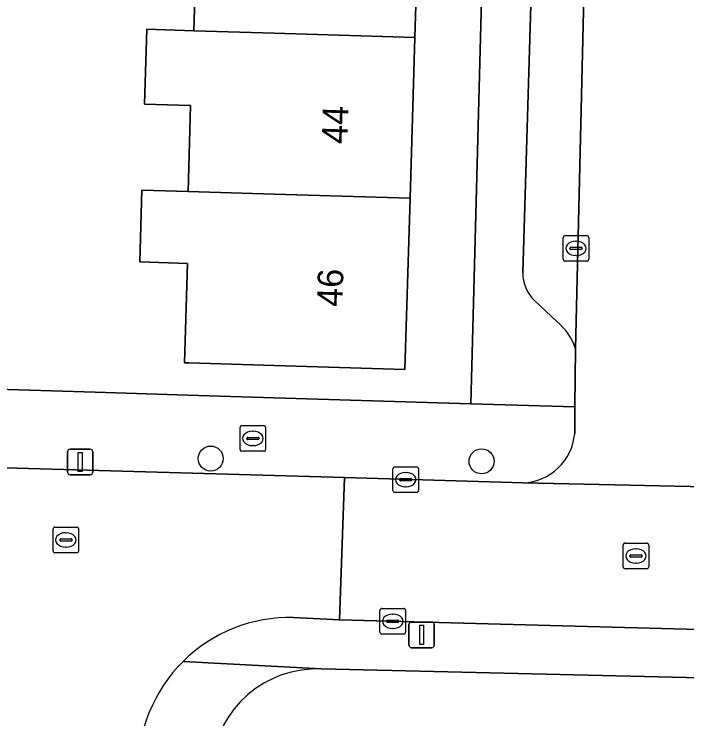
# Model space of a CAD drawing. Extents: x 162082 to 163401, y 388089 to 388636.
# Drawn here: x 162489.83 to 162516.16, y 388190.03 to 388217.6 of the extents above; entities that cross this region are included whole.
import ezdxf

# ---------------------------------------------------------------- set-up
doc = ezdxf.new("R2010")
doc.units = 0
for name, color, linetype in [('IMGEO_Boom', 7, 'Continuous'), ('IMGEO_Brandkraan', 7, 'Continuous'), ('IMGEO_Erf', 7, 'Continuous'), ('IMGEO_Groenvoorziening', 7, 'Continuous'), ('IMGEO_Kolk', 7, 'Continuous'), ('IMGEO_Lichtmast', 7, 'Continuous'), ('IMGEO_Pand', 7, 'Continuous'), ('IMGEO_Pand_nummerreeks', 7, 'Continuous'), ('IMGEO_Parkeervlak_open', 7, 'Continuous'), ('IMGEO_Rijbaan_lokaal_open', 7, 'Continuous'), ('IMGEO_Rioolput', 7, 'Continuous'), ('IMGEO_Voetpad_open', 7, 'Continuous')]:
    doc.layers.add(name, color=color, linetype=linetype)

msp = doc.modelspace()

# ---------------------------------------------------------------- linework, layer by layer
at = {"layer": 'IMGEO_Boom'}
for centre in [(162497.524, 388200.209), (162508.119, 388200.102)]:
    msp.add_circle(centre, 0.489, dxfattribs=at)
at = {"layer": 'IMGEO_Brandkraan'}
for p, q in [((162498.746, 388201.496), (162499.598, 388201.496)), ((162498.671, 388200.57), (162498.671, 388201.422)), ((162499.159, 388201.276), (162499.184, 388201.276)), ((162499.672, 388201.422), (162499.672, 388200.57)), ((162498.93, 388200.99), (162498.93, 388201.002)), ((162499.368, 388200.953), (162498.97, 388200.953)), ((162498.973, 388201.039), (162499.371, 388201.039)), ((162499.414, 388201.002), (162499.414, 388200.99)), ((162499.182, 388200.716), (162499.157, 388200.716)), ((162499.598, 388200.496), (162498.746, 388200.496))]:
    msp.add_line(p, q, dxfattribs=at)
for points in [[(162498.746, 388201.496), (162499.598, 388201.496)], [(162498.671, 388200.57), (162498.671, 388201.422)], [(162499.672, 388201.422), (162499.672, 388200.57)], [(162499.598, 388200.496), (162498.746, 388200.496)]]:
    msp.add_lwpolyline(points, dxfattribs=at)
for centre, radius, start, end in [((162498.748, 388201.42), 0.0765, 91.552, 178.448), ((162498.748, 388201.42), 0.0765, 91.552, 178.448), ((162499.596, 388201.42), 0.0765, 1.552, 88.448), ((162499.596, 388201.42), 0.0765, 1.552, 88.448), ((162498.97, 388200.999), 0.0403, 85.8775, 175.7526), ((162498.967, 388200.989), 0.0366, 178.938, 274.7102), ((162499.371, 388200.996), 0.043, 264.8664, 352.4533), ((162499.375, 388201.001), 0.0386, 1.7309, 96.639), ((162498.748, 388200.572), 0.0765, 181.552, 268.448), ((162498.748, 388200.572), 0.0765, 181.552, 268.448), ((162499.596, 388200.572), 0.0765, 271.552, 358.448), ((162499.596, 388200.572), 0.0765, 271.552, 358.448)]:
    msp.add_arc(centre, radius, start, end, dxfattribs=at)
for centre, major_axis, ratio, start_param, end_param in [((162499.158, 388200.996), (-0.387, 0.002), 0.722429, 4.712389, 7.853982), ((162499.183, 388200.996), (-0.39, 0.002), 0.717154, 1.570796, 4.712389)]:
    msp.add_ellipse(centre, major_axis=major_axis, ratio=ratio, start_param=start_param, end_param=end_param, dxfattribs=at)
at = {"layer": 'IMGEO_Erf'}
for points in [[(162488.717, 388202.931), (162492.996, 388202.801), (162496.624, 388202.69), (162500, 388202.587), (162507.697, 388202.352), (162508.569, 388235.464)], [(162505.708, 388223.014), (162505.515, 388216.682), (162505.324, 388210.391), (162505.121, 388203.697), (162500, 388203.853), (162496.665, 388203.954), (162496.498, 388203.959), (162496.616, 388207.844), (162494.747, 388207.901), (162494.832, 388210.71), (162496.635, 388210.655), (162496.737, 388214.022), (162494.928, 388214.077), (162495.017, 388217.001), (162496.862, 388216.945), (162496.967, 388220.408)]]:
    msp.add_lwpolyline(points, dxfattribs=at)
at = {"layer": 'IMGEO_Groenvoorziening'}
msp.add_lwpolyline([(162546.46, 388190.85), (162524.934, 388191.433), (162501.862, 388191.979)], dxfattribs=at)
msp.add_arc((162501.682, 388187.838), 4.145, 87.5092, 174.1806, dxfattribs=at)
at = {"layer": 'IMGEO_Kolk'}
for p, q in [((162511.39, 388208.929), (162512.242, 388208.929)), ((162511.315, 388208.003), (162511.315, 388208.855)), ((162511.803, 388208.709), (162511.828, 388208.709)), ((162512.316, 388208.855), (162512.316, 388208.003)), ((162511.574, 388208.423), (162511.574, 388208.435)), ((162512.012, 388208.386), (162511.614, 388208.386)), ((162511.617, 388208.472), (162512.015, 388208.472)), ((162512.058, 388208.435), (162512.058, 388208.423)), ((162511.826, 388208.149), (162511.801, 388208.149)), ((162512.242, 388207.929), (162511.39, 388207.929)), ((162504.653, 388198.958), (162504.653, 388199.81)), ((162504.728, 388199.884), (162505.58, 388199.884)), ((162505.654, 388199.81), (162505.654, 388198.958)), ((162505.141, 388199.664), (162505.166, 388199.664)), ((162504.912, 388199.378), (162504.912, 388199.39)), ((162505.35, 388199.341), (162504.952, 388199.341)), ((162504.955, 388199.427), (162505.353, 388199.427)), ((162505.396, 388199.39), (162505.396, 388199.378)), ((162505.164, 388199.104), (162505.139, 388199.104)), ((162505.58, 388198.884), (162504.728, 388198.884)), ((162504.221, 388194.345), (162505.073, 388194.345)), ((162504.146, 388193.419), (162504.146, 388194.271)), ((162504.634, 388194.125), (162504.659, 388194.125)), ((162505.147, 388194.271), (162505.147, 388193.419)), ((162504.405, 388193.839), (162504.405, 388193.851)), ((162504.843, 388193.802), (162504.445, 388193.802)), ((162504.448, 388193.888), (162504.846, 388193.888)), ((162504.889, 388193.851), (162504.889, 388193.839)), ((162504.657, 388193.565), (162504.632, 388193.565)), ((162505.073, 388193.345), (162504.221, 388193.345))]:
    msp.add_line(p, q, dxfattribs=at)
for points in [[(162511.39, 388208.929), (162512.242, 388208.929)], [(162511.315, 388208.003), (162511.315, 388208.855)], [(162512.316, 388208.855), (162512.316, 388208.003)], [(162512.242, 388207.929), (162511.39, 388207.929)], [(162504.653, 388198.958), (162504.653, 388199.81)], [(162504.728, 388199.884), (162505.58, 388199.884)], [(162505.654, 388199.81), (162505.654, 388198.958)], [(162505.58, 388198.884), (162504.728, 388198.884)], [(162504.221, 388194.345), (162505.073, 388194.345)], [(162504.146, 388193.419), (162504.146, 388194.271)], [(162505.147, 388194.271), (162505.147, 388193.419)], [(162505.073, 388193.345), (162504.221, 388193.345)]]:
    msp.add_lwpolyline(points, dxfattribs=at)
for centre, radius, start, end in [((162511.392, 388208.853), 0.0765, 91.552, 178.448), ((162511.392, 388208.853), 0.0765, 91.552, 178.448), ((162512.24, 388208.853), 0.0765, 1.552, 88.448), ((162512.24, 388208.853), 0.0765, 1.552, 88.448), ((162511.614, 388208.432), 0.0403, 85.8775, 175.7526), ((162511.611, 388208.422), 0.0366, 178.938, 274.7102), ((162512.015, 388208.429), 0.043, 264.8664, 352.4533), ((162512.019, 388208.434), 0.0386, 1.7309, 96.639), ((162511.392, 388208.005), 0.0765, 181.552, 268.448), ((162511.392, 388208.005), 0.0765, 181.552, 268.448), ((162512.24, 388208.005), 0.0765, 271.552, 358.448), ((162512.24, 388208.005), 0.0765, 271.552, 358.448), ((162504.73, 388199.808), 0.0765, 91.552, 178.448), ((162504.73, 388199.808), 0.0765, 91.552, 178.448), ((162505.578, 388199.808), 0.0765, 1.552, 88.448), ((162505.578, 388199.808), 0.0765, 1.552, 88.448), ((162504.952, 388199.387), 0.0403, 85.8775, 175.7526), ((162504.949, 388199.377), 0.0366, 178.938, 274.7102), ((162505.353, 388199.384), 0.043, 264.8664, 352.4533), ((162505.357, 388199.389), 0.0386, 1.7309, 96.639), ((162504.73, 388198.96), 0.0765, 181.552, 268.448), ((162504.73, 388198.96), 0.0765, 181.552, 268.448), ((162505.578, 388198.96), 0.0765, 271.552, 358.448), ((162505.578, 388198.96), 0.0765, 271.552, 358.448), ((162504.223, 388194.269), 0.0765, 91.552, 178.448), ((162504.223, 388194.269), 0.0765, 91.552, 178.448), ((162505.071, 388194.269), 0.0765, 1.552, 88.448), ((162505.071, 388194.269), 0.0765, 1.552, 88.448), ((162504.445, 388193.848), 0.0403, 85.8775, 175.7526), ((162504.442, 388193.838), 0.0366, 178.938, 274.7102), ((162504.846, 388193.845), 0.043, 264.8664, 352.4533), ((162504.85, 388193.85), 0.0386, 1.7309, 96.639), ((162504.223, 388193.421), 0.0765, 181.552, 268.448), ((162504.223, 388193.421), 0.0765, 181.552, 268.448), ((162505.071, 388193.421), 0.0765, 271.552, 358.448), ((162505.071, 388193.421), 0.0765, 271.552, 358.448)]:
    msp.add_arc(centre, radius, start, end, dxfattribs=at)
for centre, major_axis, ratio, start_param, end_param in [((162511.802, 388208.429), (-0.387, 0.002), 0.722429, 4.712389, 7.853982), ((162511.827, 388208.429), (-0.39, 0.002), 0.717154, 1.570796, 4.712389), ((162505.14, 388199.384), (-0.387, 0.002), 0.722429, 4.712389, 7.853982), ((162505.165, 388199.384), (-0.39, 0.002), 0.717154, 1.570796, 4.712389), ((162504.633, 388193.845), (-0.387, 0.002), 0.722429, 4.712389, 7.853982), ((162504.658, 388193.845), (-0.39, 0.002), 0.717154, 1.570796, 4.712389)]:
    msp.add_ellipse(centre, major_axis=major_axis, ratio=ratio, start_param=start_param, end_param=end_param, dxfattribs=at)
at = {"layer": 'IMGEO_Lichtmast'}
for p, q in [((162491.92, 388199.677), (162491.92, 388200.477)), ((162491.92, 388200.477), (162491.92, 388199.677)), ((162492.02, 388200.577), (162492.81, 388200.577)), ((162492.81, 388200.577), (162492.02, 388200.577)), ((162492.91, 388200.477), (162492.91, 388199.677)), ((162492.91, 388199.677), (162492.91, 388200.477)), ((162492.81, 388199.577), (162492.02, 388199.577)), ((162492.02, 388199.577), (162492.81, 388199.577)), ((162505.38, 388193.812), (162506.17, 388193.812)), ((162506.17, 388193.812), (162505.38, 388193.812)), ((162505.28, 388192.912), (162505.28, 388193.712)), ((162505.28, 388193.712), (162505.28, 388192.912)), ((162506.27, 388193.712), (162506.27, 388192.912)), ((162506.27, 388192.912), (162506.27, 388193.712)), ((162506.17, 388192.812), (162505.38, 388192.812)), ((162505.38, 388192.812), (162506.17, 388192.812))]:
    msp.add_line(p, q, dxfattribs=at)
for points in [[(162492.34, 388200.452), (162492.49, 388200.452), (162492.49, 388199.702), (162492.34, 388199.702), (162492.34, 388200.452)], [(162505.7, 388193.687), (162505.85, 388193.687), (162505.85, 388192.937), (162505.7, 388192.937), (162505.7, 388193.687)]]:
    msp.add_lwpolyline(points, dxfattribs=at)
for centre, start, end in [((162492.02, 388200.477), 90, 180), ((162492.02, 388200.477), 90, 180), ((162492.81, 388200.477), 0, 90), ((162492.81, 388200.477), 360, 90), ((162492.02, 388199.677), 180, 270), ((162492.02, 388199.677), 180, 270), ((162492.81, 388199.677), 270, 0), ((162492.81, 388199.677), 270, 0), ((162505.38, 388193.712), 90, 180), ((162505.38, 388193.712), 90, 180), ((162506.17, 388193.712), 0, 90), ((162506.17, 388193.712), 360, 90), ((162505.38, 388192.912), 180, 270), ((162505.38, 388192.912), 180, 270), ((162506.17, 388192.912), 270, 0), ((162506.17, 388192.912), 270, 0)]:
    msp.add_arc(centre, 0.1, start, end, dxfattribs=at)
at = {"layer": 'IMGEO_Pand'}
for points in [[(162496.862, 388216.945), (162500, 388216.85), (162505.515, 388216.682), (162505.708, 388223.014), (162500, 388223.188), (162497.078, 388223.277), (162495.183, 388223.334), (162495.096, 388220.465), (162496.967, 388220.408)], [(162505.324, 388210.391), (162505.515, 388216.682), (162500, 388216.85), (162496.862, 388216.945), (162495.017, 388217.001), (162494.928, 388214.077), (162496.737, 388214.022), (162496.635, 388210.655), (162500, 388210.553)], [(162494.747, 388207.901), (162496.616, 388207.844), (162496.498, 388203.959), (162496.665, 388203.954), (162500, 388203.853), (162505.121, 388203.697), (162505.324, 388210.391), (162500, 388210.553), (162496.635, 388210.655), (162494.832, 388210.71)]]:
    msp.add_lwpolyline(points, close=True, dxfattribs=at)
at = {"layer": 'IMGEO_Parkeervlak_open'}
for points in [[(162511.796, 388204.501), (162512.513, 388234.788)], [(162510.468, 388231.904), (162509.733, 388207.472)], [(162510.191, 388206.392), (162511.067, 388205.566)]]:
    msp.add_lwpolyline(points, dxfattribs=at)
for centre, radius, start, end in [((162511.195, 388207.455), 1.463, 179.3365, 226.6246), ((162509.635, 388203.804), 2.271, 17.8845, 50.8993)]:
    msp.add_arc(centre, radius, start, end, dxfattribs=at)
at = {"layer": 'IMGEO_Rijbaan_lokaal_open'}
for points in [[(162520.97, 388251.082), (162523.708, 388250.998), (162523.949, 388263.251), (162523.951, 388263.357), (162520.756, 388263.421), (162517.642, 388263.483), (162517.379, 388256.082), (162515.88, 388256.099), (162515.857, 388256.099), (162515.778, 388251.974), (162513.143, 388251.993), (162513.096, 388250), (162513.064, 388248.609), (162512.682, 388241.193), (162512.513, 388234.788), (162511.796, 388204.501), (162511.775, 388202.228), (162511.765, 388201.183)], [(162500.767, 388193.994), (162502.568, 388193.897), (162502.759, 388199.464), (162488.548, 388199.879), (162473.935, 388200.262), (162473.05, 388200.285), (162472.938, 388194.261), (162482.226, 388193.997), (162482.636, 388194.002)], [(162509.749, 388199.255), (162518.668, 388199.069)]]:
    msp.add_lwpolyline(points, dxfattribs=at)
msp.add_lwpolyline([(162583.027, 388197.416), (162571.264, 388197.644), (162571.167, 388197.718), (162554.857, 388198.059), (162553.864, 388198.076), (162538.01, 388198.533), (162519.576, 388198.987), (162518.668, 388199.069), (162509.749, 388199.255), (162502.759, 388199.464), (162502.568, 388193.897), (162582.601, 388191.752), (162582.769, 388195.348), (162582.974, 388195.545)], close=True, dxfattribs=at)
for centre, radius, start, end in [((162509.653, 388201.373), 2.12, 272.5848, 354.8588), ((162500.627, 388188.053), 5.942, 88.65, 134.825), ((162500.626, 388188.052), 5.943, 134.8061, 180.9792)]:
    msp.add_arc(centre, radius, start, end, dxfattribs=at)
at = {"layer": 'IMGEO_Rioolput'}
for p, q in [((162491.354, 388196.601), (162491.354, 388197.453)), ((162491.429, 388197.527), (162492.281, 388197.527)), ((162491.842, 388197.307), (162491.867, 388197.307)), ((162492.355, 388197.453), (162492.355, 388196.601)), ((162491.613, 388197.021), (162491.613, 388197.033)), ((162491.656, 388197.07), (162492.054, 388197.07)), ((162492.097, 388197.033), (162492.097, 388197.021)), ((162492.051, 388196.984), (162491.653, 388196.984)), ((162513.661, 388195.974), (162513.661, 388196.826)), ((162513.736, 388196.9), (162514.588, 388196.9)), ((162514.662, 388196.826), (162514.662, 388195.974)), ((162492.281, 388196.527), (162491.429, 388196.527)), ((162491.865, 388196.747), (162491.84, 388196.747)), ((162514.149, 388196.68), (162514.174, 388196.68)), ((162513.92, 388196.394), (162513.92, 388196.406)), ((162514.358, 388196.357), (162513.96, 388196.357)), ((162513.963, 388196.443), (162514.361, 388196.443)), ((162514.404, 388196.406), (162514.404, 388196.394)), ((162514.172, 388196.12), (162514.147, 388196.12)), ((162514.588, 388195.9), (162513.736, 388195.9))]:
    msp.add_line(p, q, dxfattribs=at)
for points in [[(162491.354, 388196.601), (162491.354, 388197.453)], [(162491.429, 388197.527), (162492.281, 388197.527)], [(162492.355, 388197.453), (162492.355, 388196.601)], [(162513.661, 388195.974), (162513.661, 388196.826)], [(162513.736, 388196.9), (162514.588, 388196.9)], [(162514.662, 388196.826), (162514.662, 388195.974)], [(162492.281, 388196.527), (162491.429, 388196.527)], [(162514.588, 388195.9), (162513.736, 388195.9)]]:
    msp.add_lwpolyline(points, dxfattribs=at)
for centre, radius, start, end in [((162491.431, 388197.451), 0.0765, 91.552, 178.448), ((162491.431, 388197.451), 0.0765, 91.552, 178.448), ((162492.279, 388197.451), 0.0765, 1.552, 88.448), ((162492.279, 388197.451), 0.0765, 1.552, 88.448), ((162491.653, 388197.03), 0.0403, 85.8775, 175.7526), ((162492.058, 388197.032), 0.0386, 1.7309, 96.639), ((162491.65, 388197.02), 0.0366, 178.938, 274.7102), ((162492.054, 388197.027), 0.043, 264.8664, 352.4533), ((162513.738, 388196.824), 0.0765, 91.552, 178.448), ((162513.738, 388196.824), 0.0765, 91.552, 178.448), ((162514.586, 388196.824), 0.0765, 1.552, 88.448), ((162514.586, 388196.824), 0.0765, 1.552, 88.448), ((162491.431, 388196.603), 0.0765, 181.552, 268.448), ((162491.431, 388196.603), 0.0765, 181.552, 268.448), ((162492.279, 388196.603), 0.0765, 271.552, 358.448), ((162492.279, 388196.603), 0.0765, 271.552, 358.448), ((162513.96, 388196.403), 0.0403, 85.8775, 175.7526), ((162513.957, 388196.393), 0.0366, 178.938, 274.7102), ((162514.361, 388196.4), 0.043, 264.8664, 352.4533), ((162514.365, 388196.405), 0.0386, 1.7309, 96.639), ((162513.738, 388195.976), 0.0765, 181.552, 268.448), ((162513.738, 388195.976), 0.0765, 181.552, 268.448), ((162514.586, 388195.976), 0.0765, 271.552, 358.448), ((162514.586, 388195.976), 0.0765, 271.552, 358.448)]:
    msp.add_arc(centre, radius, start, end, dxfattribs=at)
for centre, major_axis, ratio, start_param, end_param in [((162491.841, 388197.027), (-0.387, 0.002), 0.722429, 4.712389, 7.853982), ((162491.866, 388197.027), (-0.39, 0.002), 0.717154, 1.570796, 4.712389), ((162514.148, 388196.4), (-0.387, 0.002), 0.722429, 4.712389, 7.853982), ((162514.173, 388196.4), (-0.39, 0.002), 0.717154, 1.570796, 4.712389)]:
    msp.add_ellipse(centre, major_axis=major_axis, ratio=ratio, start_param=start_param, end_param=end_param, dxfattribs=at)
at = {"layer": 'IMGEO_Voetpad_open'}
for points in [[(162512.513, 388234.788), (162512.682, 388241.193), (162510.478, 388241.271), (162510.371, 388236.961), (162508.61, 388237.013), (162508.569, 388235.464), (162507.697, 388202.352), (162511.775, 388202.228), (162511.796, 388204.501)], [(162509.733, 388207.472), (162510.468, 388231.904)], [(162511.067, 388205.566), (162510.191, 388206.392)], [(162511.775, 388202.228), (162507.697, 388202.352), (162500, 388202.587), (162496.624, 388202.69), (162492.996, 388202.801), (162488.717, 388202.931), (162485.379, 388203.026), (162485.035, 388203.036), (162482.04, 388203.121), (162477.477, 388203.126), (162473.677, 388203.237), (162463.518, 388203.494), (162454.776, 388203.737), (162452.482, 388203.822)], [(162511.765, 388201.183), (162511.775, 388202.228)], [(162457.189, 388200.707), (162473.05, 388200.285), (162473.935, 388200.262), (162473.953, 388201.319), (162488.612, 388200.927), (162488.548, 388199.879), (162502.759, 388199.464), (162509.749, 388199.255)], [(162496.438, 388192.268), (162501.862, 388191.979), (162524.934, 388191.433), (162546.46, 388190.85), (162548.452, 388190.796), (162586.812, 388189.756), (162605.432, 388189.251), (162608.614, 388189.154), (162608.826, 388191.05), (162582.601, 388191.752), (162502.568, 388193.897)], [(162502.568, 388193.897), (162500.767, 388193.994)], [(162501.862, 388191.979), (162496.438, 388192.268)]]:
    msp.add_lwpolyline(points, dxfattribs=at)
for centre, radius, start, end in [((162511.195, 388207.455), 1.463, 179.3365, 226.6246), ((162509.635, 388203.804), 2.271, 17.8845, 50.8993), ((162509.653, 388201.373), 2.12, 272.5848, 354.8588), ((162500.627, 388188.053), 5.942, 88.65, 134.825), ((162500.626, 388188.052), 5.943, 134.8061, 180.9792), ((162501.682, 388187.838), 4.145, 87.5092, 174.1806)]:
    msp.add_arc(centre, radius, start, end, dxfattribs=at)

# ---------------------------------------------------------------- texts
at = {"layer": 'IMGEO_Pand_nummerreeks'}
for s, p in [('44', (162502.867, 388212.506)), ('46', (162502.673, 388206.133))]:
    msp.add_text(s, height=1, rotation=88.2599, dxfattribs=at).set_placement(p)

doc.saveas('drawing.dxf')
